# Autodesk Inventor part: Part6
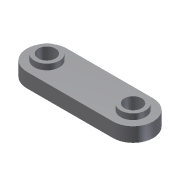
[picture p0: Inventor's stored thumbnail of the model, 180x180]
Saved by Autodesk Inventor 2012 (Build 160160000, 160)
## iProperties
Shininess: 77.0
Length Units: 11269
Angle Units: 11279
Time Units: 11290
Mass Units: 11283
Length Display Precision: 3
Angle Display Precision: 2
Created: 2002-01
Part Number: Part6
Document SubType Name: Modeling
Designer: ***
Density: 1 g/cm^3
Mass: 21.6911 g
Surface Area: 77.1136 cm^2
Volume: 21.6911 cm^3
Material: Default
Density: 0.0
Volumn: 0.0
Area: 0.0
PropertySet Name: Model Information
Control State: 0
Master: False
Checked Out: False
Author: ***
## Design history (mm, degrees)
sketch "Sketch1"
  geometry: L1 (-33.118, 12.346)-(26.882, 12.361); L2 (-33.111, -15.654)-(26.889, -15.639); C1 r 6 at (-33.114, -1.654); C2 r 6 at (26.886, -1.639); A1 r 14 centre (-33.114, -1.654) between (-33.118, 12.346) and (-33.111, -15.654); A2 r 14 centre (26.886, -1.639) between (26.889, -15.639) and (26.882, 12.361)
  constraints: 4 centre point, 4 end point, 4 point on circle, 4 tangent, 2 coincident, 2 equal radius
  dimensions: "d0" = 60 distance of L1.start L1.end; "d1" = 14 radius of A1; "d2" = 12 diameter of C1
extrude "Extrusion1" new body sketch "Sketch1" distance "d3" = 10; taper "d4" = 0 deg
sketch "Sketch2"
  geometry: C1 r 6 at (26.886, -1.639) reference; C2 r 6 at (-33.114, -1.654) reference; C3 r 8.694 at (-33.114, -1.654); C4 r 8.694 at (26.886, -1.639)
  constraints: 2 centre point, 2 coincident, 1 equal radius
extrude "Extrusion2" join sketch "Sketch2" distance "d5" = 4; taper "d6" = 0 deg
body "Solid1"
